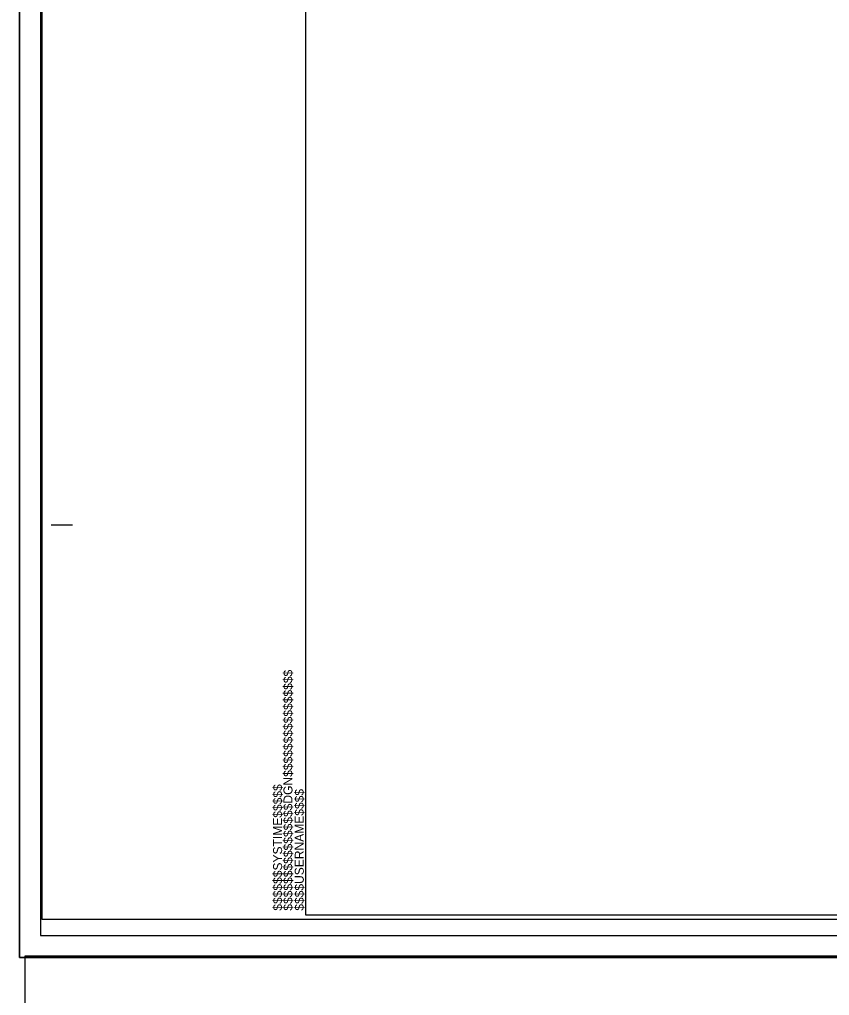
# Model space of a CAD drawing. Extents: x 2294455 to 2294795, y 719276 to 719941.
# Drawn here: x 2294454.5 to 2294549.1, y 719491.7 to 719605.6 of the extents above; entities that cross this region are included whole.
import ezdxf

# ---------------------------------------------------------------- set-up
doc = ezdxf.new("R2010")
doc.units = 0
for name, color, linetype in [('Default', 7, 'Continuous'), ('Sheet Cutting Line CELL', 7, 'Continuous'), ('Sheet Plot Border Inside CELL', 7, 'Continuous'), ('Sheet Plot Border Outside CELL', 7, 'Continuous'), ('Sheet Typical CELL', 7, 'Continuous')]:
    doc.layers.add(name, color=color, linetype=linetype)

msp = doc.modelspace()

# ---------------------------------------------------------------- linework, layer by layer
at = {"layer": 'Default'}
msp.add_lwpolyline([(2294454.52, 719716.17), (2294794.52, 719716.17), (2294794.52, 719496.17), (2294454.52, 719496.17)], close=True, dxfattribs=at)
at = {"layer": 'Sheet Cutting Line CELL'}
for p, q in [((2294791.96, 719496.34), (2294455.16, 719496.34)), ((2294455.16, 719496.34), (2294455.16, 719276.34))]:
    msp.add_line(p, q, dxfattribs=at)
at = {"layer": 'Sheet Plot Border Inside CELL'}
msp.add_lwpolyline([(2294790.42, 719711.68), (2294457.12, 719711.68), (2294457.12, 719500.66), (2294790.42, 719500.66)], close=True, dxfattribs=at)
at = {"layer": 'Sheet Plot Border Outside CELL'}
for points in [[(2294793.79, 719718.76), (2294456.99, 719718.76), (2294456.99, 719498.76), (2294793.79, 719498.76)], [(2294454.52, 719496.17), (2294791.32, 719496.17), (2294791.32, 719716.17), (2294454.52, 719716.17)], [(2294794.52, 719716.17), (2294454.52, 719716.17), (2294454.52, 719496.17), (2294794.52, 719496.17)]]:
    msp.add_lwpolyline(points, close=True, dxfattribs=at)
at = {"layer": 'Sheet Typical CELL'}
for p, q in [((2294458.22, 719546.67), (2294460.72, 719546.67)), ((2294487.92, 719501.17), (2294487.92, 719501.17)), ((2294487.92, 719501.17), (2294487.92, 719501.17)), ((2294487.92, 719501.17), (2294487.92, 719501.17)), ((2294487.92, 719501.17), (2294487.92, 719501.17)), ((2294487.92, 719501.17), (2294487.92, 719501.17)), ((2294487.92, 719501.17), (2294487.92, 719501.17))]:
    msp.add_line(p, q, dxfattribs=at)
msp.add_lwpolyline([(2294787.92, 719711.17), (2294487.92, 719711.17), (2294487.92, 719501.17), (2294787.92, 719501.17)], close=True, dxfattribs=at)
msp.add_lwpolyline([(2294495.42, 719501.17), (2294495.42, 719501.17)], dxfattribs=at)

# ---------------------------------------------------------------- texts
for s, p in [('$$$$$$$$$$$$$$$$DGN$$$$$$$$$$$$$$$$', (2294486.39, 719501.64)), ('$$$$$$SYSTIME$$$$$', (2294485.18, 719501.64)), ('$$$$USERNAME$$$$', (2294487.71, 719501.64))]:
    msp.add_text(s, height=1.05, rotation=90, dxfattribs=at).set_placement(p)

doc.saveas('drawing.dxf')
